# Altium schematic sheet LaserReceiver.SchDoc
size A; DocumentNumber: 4; SheetNumber: 4; SheetTotal: 6
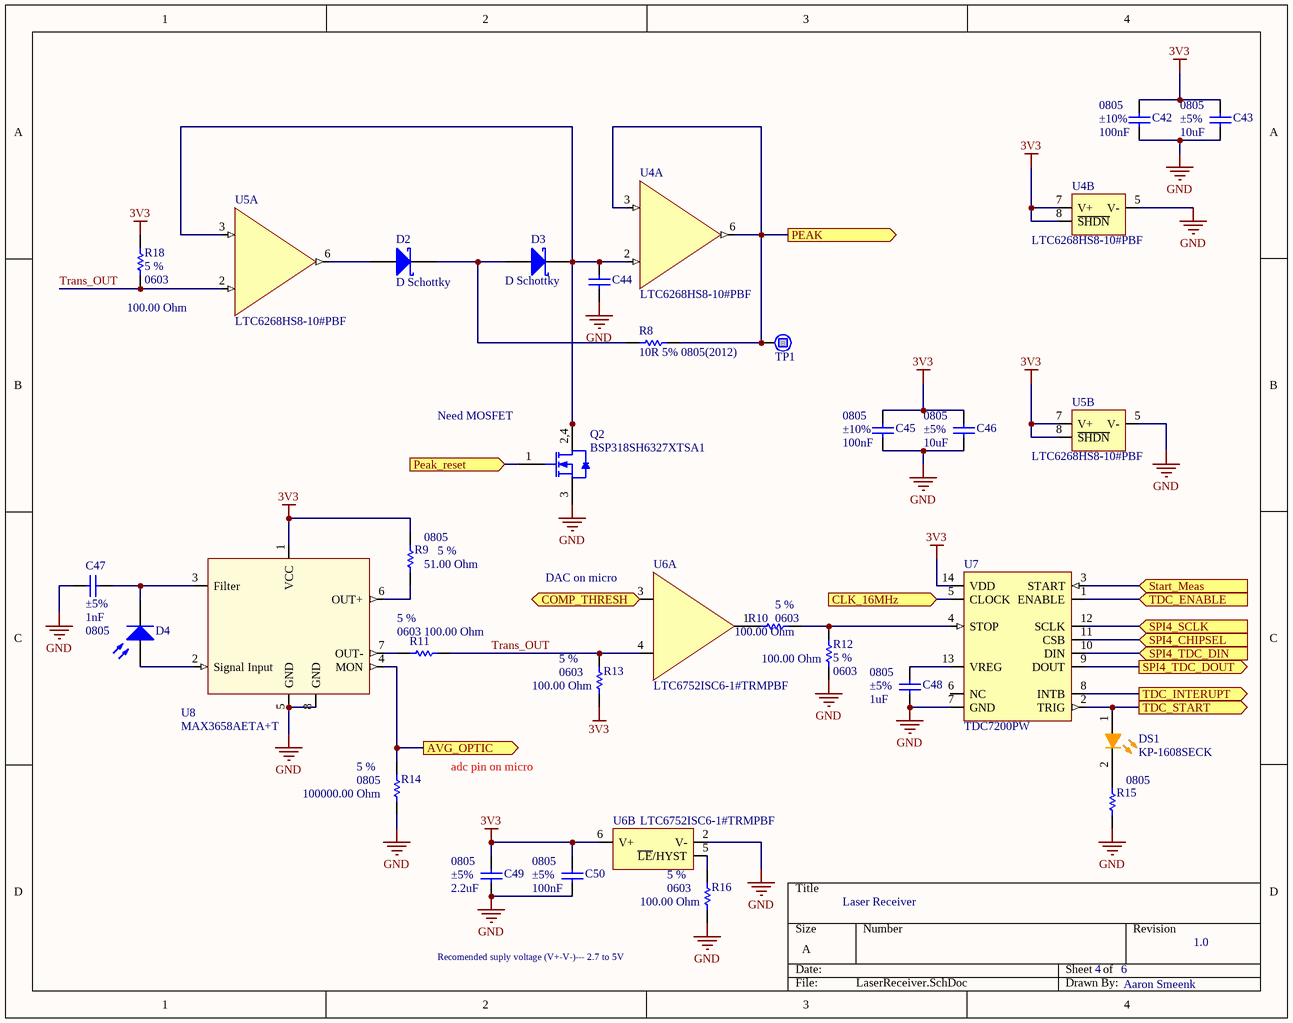
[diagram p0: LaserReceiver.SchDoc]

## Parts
C42  value 100nF  Case-EIA: 0805  Tolerance: ±10%  [CAPC0805(2012)100_N]  (hidden comment: CAP 100nF 6.3V 0805(2012))
C43  value 10uF  Case-EIA: 0805  Tolerance: ±5%  [CAPC0805(2012)145_N]  (hidden comment: CAP 10uF 6.3V 0805(2012))
C44  CAP 1nF 6.3V 0805(2012)  [CAPC0805(2012)100_M]  (value not drawn)
C45  value 100nF  Case-EIA: 0805  Tolerance: ±10%  [CAPC0805(2012)100_N]  (hidden comment: CAP 100nF 6.3V 0805(2012))
C46  value 10uF  Case-EIA: 0805  Tolerance: ±5%  [CAPC0805(2012)145_N]  (hidden comment: CAP 10uF 6.3V 0805(2012))
C47  value 1nF  Tolerance: ±5%  Case-EIA: 0805  [CAPC0805(2012)100_M]  (hidden comment: CAP 1nF 6.3V 0805(2012))
C48  value 1uF  Tolerance: ±5%  Case-EIA: 0805  [CAPC0805(2012)100_M]  (hidden comment: CAP 1uF 6.3V 0805(2012))
C49  value 2.2uF  Tolerance: ±5%  Case-EIA: 0805  [CAPC0805(2012)100_M]  (hidden comment: CAP 2.2uF 6.3V 0805(2012))
C50  value 100nF  Tolerance: ±5%  Case-EIA: 0805  [CAPC0805(2012)100_M]  (hidden comment: CAP 100nF 6.3V 0805(2012))
D2  D Schottky  [BAT6402VH6327XTSA1--DIOM1208X06N]
D3  D Schottky  [BAT6402VH6327XTSA1--DIOM1208X06N]
D4  Photo Sen  [PIN2]  (value not drawn)
DS1  KP-1608SECK  [KING-0603LED_ORANGE_V]
Q2  BSP318SH6327XTSA1  [BSP318SH6327XTSA1--SOT230P700X180-4N]
R8  10R 5% 0805(2012)  [RESC0805(2012)_L]
R9  value 51.00 Ohm  Tolerance: 5 %  Case-EIA: 0805  [RESC0805(2012)_N]  (hidden comment: 51R 5% 0805(2012))
R10  value 100.00 Ohm  Tolerance: 5 %  Case-EIA: 0603  [RESC0603(1608)_L]  (hidden comment: 100R 5% 0603(1608))
R11  value 100.00 Ohm  Tolerance: 5 %  Case-EIA: 0603  [RESC0603(1608)_L]  (hidden comment: 100R 5% 0603(1608))
R12  value 100.00 Ohm  Tolerance: 5 %  Case-EIA: 0603  [RESC0603(1608)_L]  (hidden comment: 100R 5% 0603(1608))
R13  value 100.00 Ohm  Tolerance: 5 %  Case-EIA: 0603  [RESC0603(1608)_L]  (hidden comment: 100R 5% 0603(1608))
R14  value 100000.00 Ohm  Tolerance: 5 %  Case-EIA: 0805  [RESC0805(2012)_L]  (hidden comment: 100K 5% 0805(2012))
R15  Case-EIA: 0805  [RESC0805(2012)_N]  (hidden comment: 51R 5% 0805(2012))
R16  value 100.00 Ohm  Tolerance: 5 %  Case-EIA: 0603  [RESC0603(1608)_L]  (hidden comment: 100R 5% 0603(1608))
R18  value 100.00 Ohm  Tolerance: 5 %  Case-EIA: 0603  [RESC0603(1608)_L]  (hidden comment: 100R 5% 0603(1608))
TP1  TestPoint  [TestPoint]  (value not drawn)
U4  LTC6268HS8-10#PBF  [LTC6268HS8-10#PBF--SOIC127P600X175-8N]  (parts A,B of 2)
U5  LTC6268HS8-10#PBF  [LTC6268HS8-10#PBF--SOIC127P600X175-8N]  (parts A,B of 2)
U6  LTC6752ISC6-1#TRMPBF  [LTC6752ISC6-1#TRMPBF--SOT65P210X100-6N]  (parts A,B of 2)
U7  TDC7200PW  [TDC7200PW--TSOP65P640X120-14N]
U8  MAX3658AETA+T  [MAX3658AETA+T--QFN0P300X300X80_HS-9N]

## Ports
AVG_OPTIC (out), CLK_16MHz (in), COMP_THRESH (in), PEAK (out), Peak_reset (in), SPI4_CHIPSEL (in), SPI4_SCLK (in), SPI4_TDC_DIN (in), SPI4_TDC_DOUT (out), Start_Meas (in), TDC_ENABLE (in), TDC_INTERUPT (out), TDC_START (out)

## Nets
3V3: C42.2 C43.2 C45.2 C46.2 C49.2 C50.2 R9.2 R13.1 R18.1 U4.7(V+) U4.8(~{SHDN}) U5.7(V+) U5.8(~{SHDN}) U6.6(V+) U7.14(VDD) U8.1(VCC)
GND: C42.1 C43.1 C44.1 C45.1 C46.1 C47.1 C48.1 C49.1 C50.1 Q2.3(S) R12.2 R14.1 R15.1 R16.1 U4.5(V-) U5.5(V-) U6.2(V-) U7.7(GND) U8.5(GND) U8.8(GND) U8.9(PAD)
AVG_OPTIC: R14.2 U8.4(MON) ; port AVG_OPTIC
CLK_16MHz: U7.5(CLOCK) ; port CLK_16MHz
COMP_THRESH: U6.3(IN+) ; port COMP_THRESH
PEAK: R8.2 TP1.1 U4.3(IN+) U4.6(OUT) ; port PEAK
Peak_reset: Q2.1(G) ; port Peak_reset
SPI4_CHIPSEL: U7.11(CSB) ; port SPI4_CHIPSEL
SPI4_SCLK: U7.12(SCLK) ; port SPI4_SCLK
SPI4_TDC_DIN: U7.10(DIN) ; port SPI4_TDC_DIN
SPI4_TDC_DOUT: U7.9(DOUT) ; port SPI4_TDC_DOUT
Start_Meas: U7.3(START) ; port Start_Meas
TDC_ENABLE: U7.1(ENABLE) ; port TDC_ENABLE
TDC_INTERUPT: U7.8(INTB) ; port TDC_INTERUPT
TDC_START: DS1.1(A) U7.2(TRIG) ; port TDC_START
Trans_OUT: R11.2 R13.2 R18.2 U5.2(IN-) U6.4(IN-)
NetC44_2: C44.2 D3.2(K) Q2.2(D) Q2.4(D) U4.2(IN-) U5.3(IN+)
NetC47_2: C47.2 D4.2(K) U8.3(Filter)
NetC48_2: C48.2 U7.13(VREG)
NetD2_1: D2.1(A) U5.6(OUT)
NetD2_2: D2.2(K) D3.1(A) R8.1
NetD4_1: D4.1(A) U8.2(Signal_Input)
NetDS1_2: DS1.2(K) R15.2
NetR9_1: R9.1 U8.6(OUT+)
NetR10_1: R10.1 R12.1 U7.4(STOP)
NetR10_2: R10.2 U6.1(OUT)
NetR11_1: R11.1 U8.7(OUT-)
NetR16_2: R16.2 U6.5(~{LE}/HYST)

Not connected (* = marked no-connect by the designer): U7 6(NC)

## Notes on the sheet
- (near Q2) Need MOSFET
- (near U6) DAC on micro
- adc pin on micro
- Laser Receiver
- Recomended suply voltage (V+-V-)--- 2.7 to 5V
- 4
- 6
- 1.0
- Aaron Smeenk

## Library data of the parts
C42 C45 = CMP-1036-04391-1: CAP 100nF 6.3V ±10% 0805 (2012 Metric) Thickness 1mm SMD; Case-Metric: 2012
C43 C46 = CMP-1036-04781-1: CAP 10uF 6.3V ±5% 0805 (2012 Metric) Thickness 1.45mm SMD; Case-Metric: 2012
C44 = CMP-1036-02947-1: CAP 1nF 6.3V Â±5% 0805 (2012 Metric) Thickness 1mm SMD; Case-Metric: 2012; Case-EIA: 0805
C47 = CMP-1036-02947-1: CAP 1nF 6.3V ±5% 0805 (2012 Metric) Thickness 1mm SMD; Case-Metric: 2012
C48 = CMP-1036-02947-1: CAP 1uF 6.3V ±5% 0805 (2012 Metric) Thickness 1mm SMD; Case-Metric: 2012
C49 = CMP-1036-02947-1: CAP 2.2unF 6.3V ±5% 0805 (2012 Metric) Thickness 1mm SMD; Case-Metric: 2012
C50 = CMP-1036-02947-1: CAP 100nF 6.3V ±5% 0805 (2012 Metric) Thickness 1mm SMD; Case-Metric: 2012
D2 D3 = D Schottky: Schottky Diode
D4 = Photo Sen: Photosensitive Diode
DS1 = CMP-0404-00002-1: LED, SMT, 0603(1608), 1.1mm thickness, Orange; Manufacturer: Kingbright; Power Dissipation: 75 mW; Packing Type: 2000 pcs / reel; Reverse Voltage: 5 V; Forward Current: 30 mA
Q2 = BSP318SH6327XTSA1: MOSFET N-Ch 60V 2.6A SOT-223-3
R8 = CMP-1013-00026-1: 10R 0.125W 5% 0805 (2012 Metric)  SMD; Value: 10.00 Ohm; Case-EIA: 0805; Case-Metric: 2012
R9 = CMP-1013-00043-1: 51R 0.125W 5% 0805 (2012 Metric)  SMD; Case-Metric: 2012
R10-R13 R16 R18 = CMP-1012-00050-1: 100R 0.1W 5% 0603 (1608 Metric)  SMD; Case-Metric: 1608
R14 = CMP-1013-00122-1: 100K 0.125W 5% 0805 (2012 Metric)  SMD; Case-Metric: 2012
R15 = CMP-1013-00043-1: 51R 0.125W 5% 0805 (2012 Metric)  SMD; Value: 51.00 Ohm; Case-Metric: 2012
U4 U5 = LTC6268HS8-10#PBF: IC OPAMP 4GHZ SGL FET 8SOIC
U6 = LTC6752ISC6-1#TRMPBF: IC COMP R-R CMOS 280MHZ SC70-6
U7 = TDC7200PW: STATIC ULTRASONIC FLOWMETER AF
U8 = MAX3658AETA+T: IC AMP TRANSIMPEDANCE 8-TDFN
